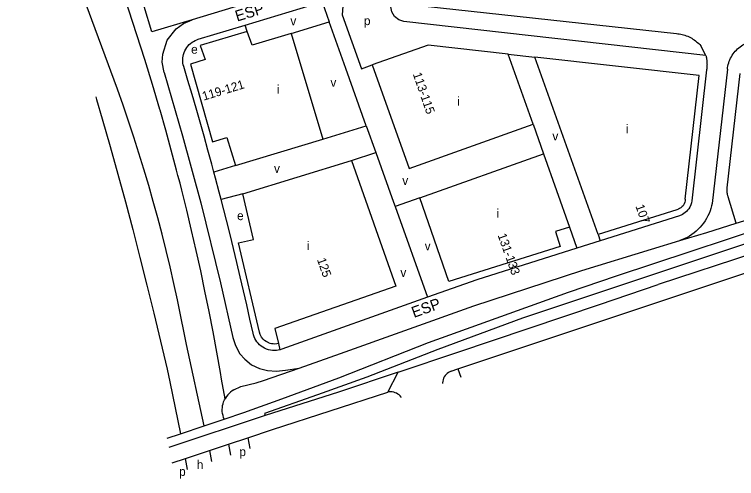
# Model space of a CAD drawing. Extents: x 161394 to 163917, y 388470 to 389774.
# Drawn here: x 162013.8 to 162341, y 388470.5 to 388680.9 of the extents above; entities that cross this region are included whole.
import ezdxf

# ---------------------------------------------------------------- set-up
doc = ezdxf.new("R2010")
doc.units = 0
for name, color, linetype in [('BLT_Basislijn', 7, 'Continuous'), ('BLT_Bebouwing', 7, 'Continuous'), ('BLT_Centroide', 7, 'Continuous'), ('BLT_Huisnummer', 7, 'Continuous'), ('BLT_Huisnummer_reeks', 7, 'Continuous'), ('BLT_Straatnaam', 7, 'Continuous'), ('BLT_Vlakafsluiter', 7, 'Continuous')]:
    doc.layers.add(name, color=color, linetype=linetype)

msp = doc.modelspace()

# ---------------------------------------------------------------- linework, layer by layer
at = {"layer": 'BLT_Basislijn'}
for p, q in [((162119.24, 388673.22), (162118.23, 388676.05)), ((162139.07, 388672.24), (162156.39, 388677.5)), ((162327.03, 388662.28), (162190.14, 388677.75)), ((162327.03, 388662.28), (162324.7, 388666.71)), ((162237.45, 388662.85), (162249.59, 388661.57)), ((162336.78, 388656.04), (162329.9, 388595.22)), ((162336.75, 388602.35), (162342.6, 388654.12)), ((162153.52, 388624.41), (162173.18, 388630.39)), ((162248.8, 388631.11), (162253.52, 388617.68)), ((162166.51, 388614.64), (162177.5, 388618.24)), ((162113.88, 388612.36), (162104.15, 388609.41)), ((162117.23, 388599.58), (162107.42, 388597.05)), ((162197.44, 388597.74), (162186.21, 388593.75)), ((162265.26, 388584.52), (162268.65, 388574.93)), ((162382.33, 388583.76), (162305.41, 388558.5)), ((162278.24, 388581.06), (162279.13, 388578.24)), ((162214.71, 388520.22), (162377.39, 388574.62)), ((162270.91, 388564.75), (162302.38, 388574.44)), ((162133.38, 388531.67), (162134.04, 388528.85)), ((162211.62, 388519.19), (162214.71, 388520.22)), ((162214.71, 388520.22), (162216.04, 388516.41)), ((162108.81, 388497.45), (162117.76, 388500.47))]:
    msp.add_line(p, q, dxfattribs=at)
for points in [[(162087.86, 388607.87), (162087.24, 388610.3), (162084.83, 388619.37), (162082.34, 388628.43), (162079.77, 388637.46), (162079.66, 388637.83), (162076.25, 388649.13), (162072.76, 388660.41), (162069.19, 388671.66), (162065.55, 388682.89), (162061.84, 388694.09), (162058.05, 388705.27), (162054.18, 388716.42), (162050.23, 388727.55), (162046.22, 388738.65), (162042.12, 388749.72), (162038.47, 388758.81), (162033.68, 388770.55), (162028.82, 388782.27), (162023.88, 388793.95), (162018.87, 388805.6), (162013.78, 388817.22), (162008.62, 388828.81), (162003.19, 388840.81)], [(162099.69, 388494.38), (162091.65, 388531.25), (162090.66, 388536.53), (162089.19, 388544.02), (162087.64, 388551.5), (162086, 388558.97), (162084.3, 388566.41), (162082.51, 388573.84), (162080.64, 388581.25), (162078.7, 388588.64), (162076.68, 388596.01), (162074.59, 388603.36), (162072.41, 388610.68), (162070.16, 388617.98), (162067.84, 388625.26), (162065.43, 388632.51), (162062.96, 388639.74), (162060.4, 388646.94), (162036.19, 388712.95), (162022.35, 388749.92), (162021.79, 388751.4), (162017.9, 388761.55), (162013.94, 388771.67), (162009.9, 388781.76)], [(162076.06, 388672.96), (162072.49, 388684.45), (162070.66, 388690.18), (162069.74, 388693.05), (162068.81, 388695.91), (162067.87, 388698.77), (162066.93, 388701.62), (162065.98, 388704.48), (162065.02, 388707.33), (162064.05, 388710.18), (162063.08, 388713.03), (162062.1, 388715.87), (162061.12, 388718.72), (162060.13, 388721.56), (162059.13, 388724.4), (162058.12, 388727.23), (162059.13, 388728.01)], [(162156.12, 388697.27), (162094.32, 388678.5)], [(162162.85, 388688.54), (162162.3, 388680.7), (162171.01, 388656.24), (162175.86, 388657.98)], [(162118.23, 388676.05), (162153.13, 388686.65)], [(162153.13, 388686.65), (162156.39, 388677.5)], [(162190.14, 388677.75), (162187.93, 388678.41), (162185.98, 388679.93), (162184.73, 388682.07), (162184.37, 388684.35), (162184.54, 388686.31)], [(162184.54, 388686.31), (162313.68, 388672.24)], [(162094.32, 388678.5), (162076.06, 388672.96)], [(162081.54, 388654.54), (162080.75, 388659.24), (162080.92, 388662.81), (162082.92, 388669.17), (162087.02, 388674.4), (162090.41, 388676.75), (162094.32, 388678.5)], [(162097.03, 388669.61), (162118.23, 388676.05)], [(162313.68, 388672.24), (162314.33, 388672.17), (162314.98, 388672.08), (162315.63, 388671.97), (162316.28, 388671.82), (162316.92, 388671.65), (162317.56, 388671.45), (162318.19, 388671.23), (162318.81, 388670.98), (162319.43, 388670.7), (162320.03, 388670.4), (162320.62, 388670.07), (162321.19, 388669.72), (162321.75, 388669.35), (162322.29, 388668.95), (162322.81, 388668.54), (162323.32, 388668.11), (162323.8, 388667.66), (162324.26, 388667.19), (162324.7, 388666.71)], [(162090.43, 388657.25), (162090.24, 388657.97), (162090.11, 388658.73), (162090.02, 388659.52), (162090.01, 388660.32), (162090.06, 388661.15), (162090.18, 388661.98), (162090.37, 388662.8), (162090.64, 388663.62), (162090.98, 388664.41), (162091.38, 388665.17), (162091.85, 388665.89), (162092.38, 388666.57), (162092.96, 388667.19), (162093.58, 388667.75), (162094.24, 388668.25), (162094.92, 388668.69), (162095.62, 388669.06), (162096.32, 388669.36), (162097.03, 388669.61)], [(162336.78, 388656.04), (162336.88, 388656.76), (162337.01, 388657.48), (162337.19, 388658.2), (162337.4, 388658.92), (162337.64, 388659.63), (162337.93, 388660.34), (162338.25, 388661.02), (162338.6, 388661.7), (162339, 388662.36), (162339.42, 388662.99), (162339.88, 388663.61), (162340.36, 388664.2), (162340.88, 388664.76), (162341.41, 388665.29), (162341.98, 388665.79), (162342.56, 388666.26), (162343.16, 388666.7), (162343.77, 388667.1), (162344.4, 388667.47)], [(162327.03, 388662.28), (162327.12, 388661.95), (162327.19, 388661.62), (162327.26, 388661.28), (162327.33, 388660.95), (162327.38, 388660.61), (162327.43, 388660.27), (162327.47, 388659.93), (162327.5, 388659.59), (162327.53, 388659.25), (162327.55, 388658.91), (162327.56, 388658.56), (162327.57, 388658.22), (162327.56, 388657.88), (162327.55, 388657.54), (162327.54, 388657.2), (162327.51, 388656.86), (162327.48, 388656.52), (162327.44, 388656.18), (162327.4, 388655.84)], [(162104.15, 388609.41), (162103.18, 388613.01), (162101.44, 388619.36), (162099.68, 388625.69), (162097.89, 388632.02), (162096.06, 388638.34), (162094.21, 388644.65), (162092.34, 388650.96), (162090.43, 388657.25)], [(162327.4, 388655.84), (162320.67, 388596.35)], [(162081.54, 388654.54), (162089.97, 388625.82), (162098.24, 388595.45), (162107.11, 388559.18), (162112.78, 388534.37)], [(162050.58, 388643.56), (162050.96, 388642.28), (162053.54, 388633.62), (162057.11, 388621.08), (162060.6, 388608.52), (162064.02, 388595.94), (162067.36, 388583.34), (162070.62, 388570.72), (162073.8, 388558.08), (162076.91, 388545.42), (162079.93, 388532.74), (162082.89, 388520.04), (162084.19, 388514.31), (162088.97, 388490.77)], [(162461.09, 388631.3), (162452.6, 388623.68), (162444.16, 388617.01), (162435.81, 388611.92), (162423.79, 388605.68), (162414.47, 388601.04), (162405.41, 388597.44), (162396.96, 388593.99), (162347.65, 388577.75), (162243.97, 388543.13), (162205.6, 388529.01), (162173.35, 388516.42), (162151.08, 388508.41), (162127, 388500), (162127.4, 388499.02)], [(162173.18, 388630.39), (162177.5, 388618.24)], [(162177.5, 388618.24), (162185.49, 388595.76), (162186.21, 388593.75)], [(162107.42, 388597.05), (162106.57, 388600.3), (162104.89, 388606.66), (162104.15, 388609.41)], [(162109.18, 388506.64), (162107.61, 388515.53), (162107.09, 388518.56), (162105.46, 388527.81), (162103.75, 388537.04), (162101.96, 388546.26), (162100.09, 388555.46), (162098.14, 388564.64), (162096.12, 388573.81), (162094.01, 388582.96), (162091.83, 388592.09), (162089.58, 388601.21), (162088.78, 388604.32), (162087.86, 388607.87)], [(162286.6, 388562.38), (162370.69, 388590.23), (162399.53, 388600.27)], [(162337.15, 388598.17), (162337.09, 388598.38), (162337.03, 388598.6), (162336.97, 388598.81), (162336.92, 388599.03), (162336.88, 388599.25), (162336.84, 388599.47), (162336.8, 388599.68), (162336.77, 388599.91), (162336.75, 388600.13), (162336.73, 388600.35), (162336.71, 388600.57), (162336.7, 388600.79), (162336.69, 388601.02), (162336.69, 388601.24), (162336.69, 388601.46), (162336.7, 388601.68), (162336.71, 388601.9), (162336.73, 388602.12), (162336.75, 388602.35)], [(162121.85, 388536.33), (162120.45, 388542.76), (162119.02, 388549.17), (162117.57, 388555.59), (162116.08, 388561.99), (162114.57, 388568.4), (162113.02, 388574.79), (162111.45, 388581.18), (162109.86, 388587.56), (162107.42, 388597.05)], [(162320.67, 388596.35), (162320.49, 388595.46), (162320.18, 388594.52), (162319.75, 388593.56), (162319.28, 388592.8), (162318.79, 388592.16), (162318.2, 388591.52), (162317.65, 388591.04), (162317.02, 388590.57), (162316.47, 388590.21), (162315.84, 388589.88), (162315.4, 388589.72), (162315.12, 388589.61)], [(162340.8, 388586.23), (162337.15, 388598.17)], [(162340.8, 388586.23), (162348.14, 388588.53), (162364.48, 388593.58), (162365.51, 388593.94), (162373.99, 388596.95)], [(162186.21, 388593.75), (162200.96, 388552.65)], [(162329.9, 388595.22), (162329.64, 388594.07), (162329.32, 388592.92), (162328.93, 388591.78), (162328.48, 388590.64), (162327.96, 388589.53), (162327.37, 388588.43), (162326.72, 388587.37), (162326.02, 388586.33), (162325.25, 388585.34), (162324.43, 388584.39), (162323.55, 388583.49), (162322.64, 388582.64), (162321.67, 388581.85), (162320.68, 388581.11), (162319.65, 388580.43), (162318.59, 388579.82), (162317.51, 388579.27), (162316.42, 388578.78), (162315.32, 388578.36)], [(162315.12, 388589.61), (162279.13, 388578.24)], [(162315.32, 388578.36), (162327.56, 388582.07), (162340.8, 388586.23)], [(162279.13, 388578.24), (162268.65, 388574.93)], [(162302.38, 388574.44), (162315.32, 388578.36)], [(162268.65, 388574.93), (162223.3, 388560.62), (162200.96, 388552.65)], [(162142.8, 388520.59), (162161.56, 388527.21), (162221.88, 388548.81), (162270.91, 388564.75)], [(162117.76, 388500.47), (162134.93, 388506.62), (162160.76, 388516.11), (162201.4, 388532.18), (162264.8, 388554.97), (162286.6, 388562.38)], [(162187.61, 388518.75), (162214.62, 388527.82), (162278.78, 388549.41), (162305.41, 388558.5)], [(162200.96, 388552.65), (162134.85, 388529.1)], [(162112.78, 388534.37), (162113.9, 388530.74), (162115.91, 388526.99), (162118.09, 388524.55), (162121.13, 388522.11), (162124.79, 388520.37), (162128.45, 388519.41), (162132.54, 388519.15), (162136.58, 388519.57), (162142.8, 388520.59)], [(162134.04, 388528.85), (162133.29, 388528.68), (162132.45, 388528.56), (162131.58, 388528.52), (162130.69, 388528.56), (162129.78, 388528.68), (162128.88, 388528.88), (162127.99, 388529.17), (162127.13, 388529.55), (162126.31, 388530.01), (162125.53, 388530.54), (162124.82, 388531.14), (162124.17, 388531.8), (162123.59, 388532.5), (162123.09, 388533.24), (162122.67, 388534.01), (162122.32, 388534.78), (162122.05, 388535.56), (162121.85, 388536.33)], [(162134.85, 388529.1), (162134.09, 388528.86), (162134.04, 388528.85)], [(162113.18, 388510.7), (162116.37, 388512.27), (162123.23, 388513.89), (162126.66, 388514.9), (162142.8, 388520.59)], [(162187.61, 388518.75), (162160.59, 388509.69), (162127.4, 388499.02)], [(162211.62, 388519.19), (162210.99, 388518.91), (162210.39, 388518.56), (162209.84, 388518.15), (162209.34, 388517.67), (162208.89, 388517.14), (162208.51, 388516.56), (162208.2, 388515.94), (162207.97, 388515.29), (162207.81, 388514.62), (162207.72, 388513.93), (162207.72, 388513.6)], [(162113.18, 388510.7), (162112.41, 388510.22), (162111.68, 388509.67), (162111.01, 388509.07), (162110.38, 388508.4), (162109.83, 388507.68), (162109.33, 388506.92), (162109.18, 388506.64)], [(162119.49, 388488.99), (162130.69, 388492.71), (162182.91, 388509.6)], [(162189.03, 388507.27), (162188.94, 388507.4), (162188.51, 388507.93), (162188.02, 388508.39), (162187.47, 388508.8), (162186.88, 388509.14), (162186.26, 388509.41), (162185.61, 388509.61), (162184.94, 388509.72), (162184.26, 388509.76), (162183.58, 388509.72), (162182.91, 388509.6)], [(162108.81, 388497.45), (162108.53, 388498.15), (162108.26, 388499.02), (162108.06, 388499.91), (162107.94, 388500.81), (162107.91, 388501.72), (162107.95, 388502.63), (162108.07, 388503.53), (162108.27, 388504.41), (162108.55, 388505.28), (162108.9, 388506.12), (162109.18, 388506.64)], [(162127.4, 388499.02), (162083.78, 388484.62)], [(162099.69, 388494.38), (162108.81, 388497.45)], [(162088.97, 388490.77), (162099.69, 388494.38)], [(162082.92, 388488.74), (162088.97, 388490.77)], [(162110.67, 388486.06), (162119.49, 388488.99)], [(162119.49, 388488.99), (162120.42, 388484.06)], [(162102.1, 388483.22), (162110.67, 388486.06)], [(162110.67, 388486.06), (162111.61, 388481.08)], [(162091.24, 388479.61), (162102.1, 388483.22)], [(162102.1, 388483.22), (162102.11, 388483.17)], [(162102.11, 388483.17), (162103.05, 388478.18)], [(162085.24, 388477.62), (162091.24, 388479.61)], [(162091.25, 388479.56), (162091.24, 388479.61)], [(162092.2, 388474.51), (162091.25, 388479.56)]]:
    msp.add_lwpolyline(points, dxfattribs=at)
at = {"layer": 'BLT_Bebouwing'}
for p, q in [((162139.07, 388672.24), (162153.52, 388624.41)), ((162324.03, 388653.19), (162249.59, 388661.57)), ((162278.24, 388581.06), (162249.59, 388661.57)), ((162317.74, 388597.16), (162324.03, 388653.19)), ((162313.95, 388592.38), (162278.24, 388581.06))]:
    msp.add_line(p, q, dxfattribs=at)
for points in [[(162163.9, 388656.42), (162156.39, 388677.5)], [(162119.24, 388673.22), (162097.98, 388666.76), (162100.23, 388660.44), (162093.53, 388658.41), (162103.49, 388623.19), (162109.98, 388625.16), (162113.88, 388612.36)], [(162139.07, 388672.24), (162121.49, 388666.9), (162119.24, 388673.22)], [(162237.45, 388662.85), (162201.17, 388666.99), (162175.86, 388657.98)], [(162248.8, 388631.11), (162237.45, 388662.85)], [(162173.18, 388630.39), (162163.9, 388656.42)], [(162175.86, 388657.98), (162192.55, 388611.08)], [(162192.55, 388611.08), (162248.8, 388631.11)], [(162113.88, 388612.36), (162153.52, 388624.41)], [(162197.44, 388597.74), (162253.52, 388617.68)], [(162253.52, 388617.68), (162265.26, 388584.52)], [(162117.23, 388599.58), (162166.51, 388614.64)], [(162166.51, 388614.64), (162186.52, 388557.65), (162131.78, 388538.55), (162133.38, 388531.67)], [(162133.38, 388531.67), (162132.63, 388531.51), (162131.69, 388531.43), (162130.97, 388531.5), (162130.21, 388531.58), (162129.56, 388531.76), (162128.91, 388531.99), (162128.37, 388532.25), (162127.78, 388532.58), (162127.11, 388533.09), (162126.47, 388533.72), (162125.76, 388534.62), (162125.16, 388535.72), (162124.81, 388536.8), (162115.31, 388577.31), (162122.08, 388578.89), (162117.23, 388599.58)], [(162265.26, 388584.52), (162258.9, 388582.53), (162261.06, 388575.68), (162210.55, 388559.77), (162197.44, 388597.74)], [(162317.74, 388597.16), (162317.69, 388596.46), (162317.54, 388595.75), (162317.27, 388595.09), (162317.11, 388594.79), (162316.74, 388594.18), (162316.35, 388593.75), (162316.07, 388593.49), (162315.73, 388593.21), (162315.17, 388592.86), (162314.61, 388592.58), (162313.95, 388592.38)]]:
    msp.add_lwpolyline(points, dxfattribs=at)
at = {"layer": 'BLT_Vlakafsluiter'}
msp.add_line((162091.25, 388479.56), (162102.11, 388483.17), dxfattribs=at)
msp.add_lwpolyline([(162182.91, 388509.6), (162187.61, 388518.75)], dxfattribs=at)

# ---------------------------------------------------------------- texts
at = {"layer": 'BLT_Centroide'}
for s, p in [('v', (162138.78, 388675.98)), ('p', (162172.1, 388676.05)), ('e', (162093.81, 388663.09)), ('i', (162132.67, 388644.94)), ('v', (162156.93, 388648.08)), ('i', (162214.39, 388639.53)), ('i', (162290.78, 388627.05)), ('v', (162257.51, 388623.75)), ('v', (162131.37, 388609.07)), ('v', (162189.5, 388603.59)), ('i', (162232.16, 388588.72)), ('e', (162114.64, 388587.64)), ('i', (162146.22, 388574.03)), ('v', (162199.65, 388573.97)), ('v', (162188.64, 388561.91)), ('p', (162115.67, 388480.65)), ('h', (162096.37, 388474.79)), ('p', (162088.37, 388471.68))]:
    msp.add_text(s, height=4, dxfattribs=at).set_placement(p)
at = {"layer": 'BLT_Huisnummer'}
for s, rotation, p in [('107', 289.4936, (162295.07, 388594.01)), ('125', 289.0501, (162150.8, 388569.78))]:
    msp.add_text(s, height=4, rotation=rotation, dxfattribs=at).set_placement(p)
at = {"layer": 'BLT_Huisnummer_reeks'}
for s, rotation, p in [('113-115', 289.0498, (162194.21, 388653.87)), ('119-121', 16.8966, (162099.5, 388641.79)), ('131-133', 289.6145, (162232.63, 388580.84))]:
    msp.add_text(s, height=4, rotation=rotation, dxfattribs=at).set_placement(p)
at = {"layer": 'BLT_Straatnaam'}
for rotation, p in [(16.8942, (162114.62, 388677.61)), (19.6988, (162194.75, 388543.28))]:
    msp.add_text('ESP', height=5, rotation=rotation, dxfattribs=at).set_placement(p)

doc.saveas('drawing.dxf')
